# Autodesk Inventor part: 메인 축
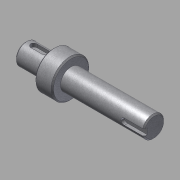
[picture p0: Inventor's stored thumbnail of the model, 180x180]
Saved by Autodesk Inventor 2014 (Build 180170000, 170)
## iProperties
Created: 2014-10
Part Number: 메인 축
Document SubType Name: Modeling
Designer: KYOUNG IL JANG
Density: 7.86 g/cm^3
Mass: 230.24 g
Surface Area: 74.3518 cm^2
Volume: 29.2926 cm^3
Material: 강철, 연강
Appearance: 금속-강(스테인리스, 브러시됨)
Author: SeoGD™ [www.esajin.kr]
Revision Number: 1
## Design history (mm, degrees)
sketch "스케치1"
  geometry: L1 (10.497, -57.5)-(112.497, -57.5); L2 (10.497, -66)-(32.497, -66); L3 (32.497, -72.5)-(46.5, -72.5); L4 (46.5, -66)-(112.497, -66); L5 (112.497, -66)-(112.497, -57.5); L6 (10.497, -66)-(10.497, -57.5); L7 (46.5, -69.749)-(46.5, -45.251) reference; L8 (46.5, -72.5)-(46.5, -66); L9 (32.497, -72.5)-(32.497, -66); L10 (32.497, -35)-(32.497, -80) reference; 3 further points
  constraints: 16 end point, 3 point on line, 2 parallel, 2 perpendicular, 1 collinear, 1 horizontal, 1 midpoint
  dimensions: "d0" = 17 diameter of L4 L1; "d1" = 30 diameter of L3 L1; "d2" = 22 distance of L2.start L2.end; "d3" = 65.99692 distance of L4.start L4.end (derived); "d5" = 17 diameter of L2 L1; "d19" = 80 distance between parallel lines of L5 L9
revolve "회전1" sketch "스케치1" stored, may be unused: angle "d4" = 90 deg
chamfer "모따기1" distance "d6" = 1; stored, may be unused: second distance "d7" = 2, angle "d8" = 45 deg
node "작업 평면1"
sketch "스케치2"
  geometry: L1 (-11, -7.5)-(-11, 7.5) reference; L2 (-4.5, 2.5)-(4.5, 2.5); L3 (4.5, -2.5)-(-4.5, -2.5); A1 r 2.5 centre (4.5, 0) between (4.5, -2.5) and (4.5, 2.5); A2 r 2.5 centre (-4.5, 0) between (-4.5, 2.5) and (-4.5, -2.5); 2 further points
  constraints: 4 end point, 4 point on circle, 4 tangent, 2 centre point, 1 horizontal alignment, 1 midpoint, 1 parallel, 1 perpendicular
  dimensions: "d9" = 5 distance between parallel lines of L3 L2; "d10" = 14 dimension on A1 A2; "d11" = 4 distance edge to line of A2 L1
extrude "돌출1" cut sketch "스케치2" distance "d12" = 3; taper "d13" = 0 deg
node "작업 평면2"
sketch "스케치3"
  geometry: L1 (32.998, 7.5)-(32.998, -7.5) reference; L2 (32.998, 2.5)-(17.498, 2.5); L3 (17.498, -2.5)-(32.998, -2.5); A1 r 2.5 centre (17.498, 0) between (17.498, 2.5) and (17.498, -2.5); 2 further points
  constraints: 4 end point, 2 perpendicular, 2 point on circle, 2 point on line, 2 tangent, 1 centre point, 1 horizontal alignment, 1 midpoint
  dimensions: "d14" = 5 distance between parallel lines of L3 L2; "d15" = 18 dimension on A1 L1
extrude "돌출2" cut sketch "스케치3" distance "d16" = 3; taper "d17" = 0 deg
node "솔리드1"
node "참조4"
node "참조5"
